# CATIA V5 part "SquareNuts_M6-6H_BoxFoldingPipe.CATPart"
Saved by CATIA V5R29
Part number: SquareNuts_M6-6H_BoxFoldingPipe
Source: Unknown
Bounding box of the stored display mesh (mm): x -7 to 7, y -7 to 7, z -3 to 3
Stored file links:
  C:\가치같이\SmartFactory_BoxErectorConveyor\Boxing(under)\SquareNuts_M6-6H_BoxFoldingPipe.CATPart
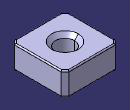
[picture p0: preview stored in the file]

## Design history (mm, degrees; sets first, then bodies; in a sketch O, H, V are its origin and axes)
Body1 (main body)
  Solid1 "PartBody": solid without history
